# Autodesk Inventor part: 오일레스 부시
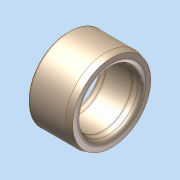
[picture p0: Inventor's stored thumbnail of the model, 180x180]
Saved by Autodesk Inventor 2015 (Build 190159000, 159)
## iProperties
Created: 2024-06
Part Number: 오일레스 부시
Material: 일반
Document SubType Name: Modeling
Designer: Administrator
Density: 1 g/cm^3
Appearance: 기본값
Author: Administrator
Author: jhkim
Creation Date: 2024-05-29
Sending System: Autodesk Inventor 2025
Preprocessor: ST-DEVELOPER v20
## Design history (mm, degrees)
node "오일레스 부시1"
node "솔리드1"
node "기준1"
